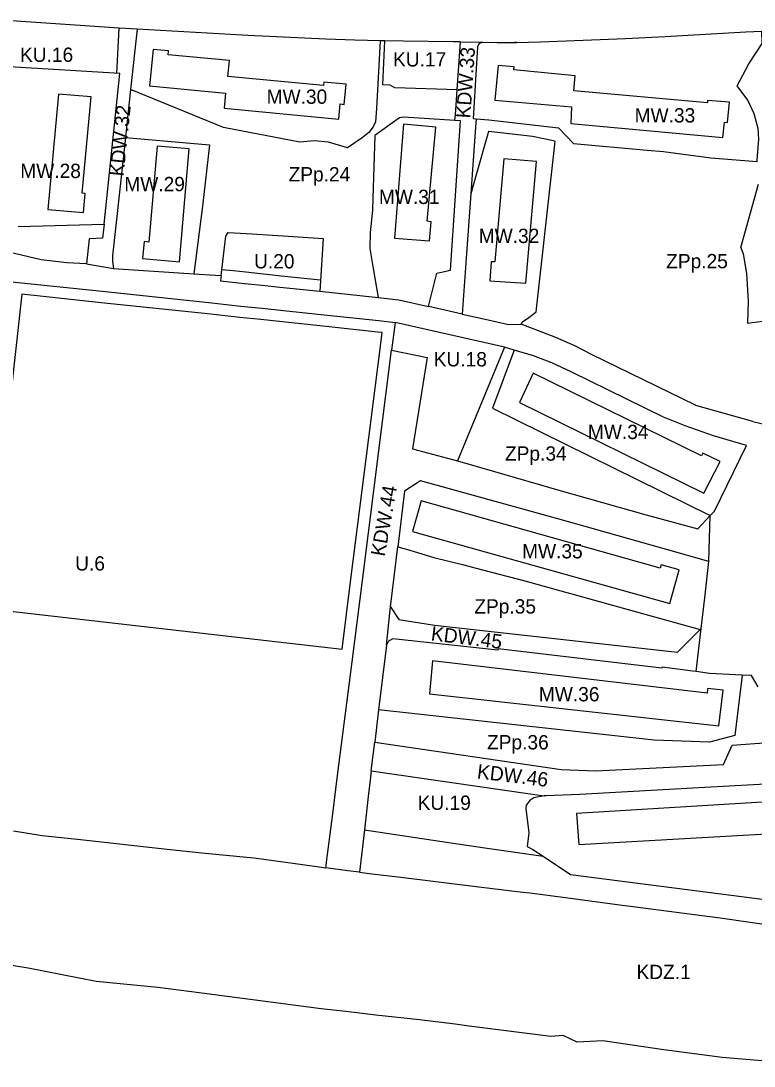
# Model space of a CAD drawing. Extents: x 7424434 to 7425898, y 5541432 to 5542659.
# Drawn here: x 7424993.9 to 7425250.1, y 5541470.1 to 5541835.1 of the extents above; entities that cross this region are included whole.
import ezdxf

# ---------------------------------------------------------------- set-up
doc = ezdxf.new("R2010")
doc.units = 0
for name, color, linetype in [('linie rozgraniczające', 7, 'Continuous'), ('nieprzekraczalne linie zabudowy', 7, 'Continuous'), ('obowiazujace linie zabudowy', 7, 'Continuous'), ('przeznaczenia terenów', 7, 'Continuous')]:
    doc.layers.add(name, color=color, linetype=linetype)

msp = doc.modelspace()

# ---------------------------------------------------------------- linework, layer by layer
at = {"layer": 'linie rozgraniczające'}
for p, q in [((7425028.31, 5541832.6), (7424990.69, 5541835.14)), ((7425027.41, 5541816.82), (7425028.31, 5541832.6)), ((7425034.51, 5541832.21), (7425028.31, 5541832.6)), ((7425034.51, 5541832.21), (7425032.26, 5541811.15)), ((7425071.28, 5541830.18), (7425034.51, 5541832.21)), ((7425073.25, 5541830.08), (7425071.28, 5541830.18)), ((7425100.46, 5541828.73), (7425073.25, 5541830.08)), ((7425110.62, 5541828.41), (7425100.46, 5541828.73)), ((7425119.42, 5541828.23), (7425110.62, 5541828.41)), ((7425119.42, 5541828.23), (7425118.19, 5541804.6)), ((7425121.11, 5541828.19), (7425119.42, 5541828.23)), ((7425120.42, 5541812.76), (7425121.11, 5541828.19)), ((7425127.58, 5541828.06), (7425121.11, 5541828.19)), ((7425144.98, 5541827.83), (7425127.58, 5541828.06)), ((7425147.53, 5541827.8), (7425144.98, 5541827.83)), ((7425146.35, 5541811.09), (7425147.53, 5541827.8)), ((7425147.53, 5541827.8), (7425155.16, 5541827.7)), ((7425153.88, 5541827.17), (7425153.49, 5541826.05)), ((7425155.16, 5541827.7), (7425153.88, 5541827.17)), ((7425167.04, 5541827.57), (7425166.42, 5541827.54)), ((7425153.49, 5541826.05), (7425151.91, 5541801.1)), ((7425028.52, 5541816.75), (7424990.01, 5541819.09)), ((7425023, 5541764.15), (7425028.52, 5541816.75)), ((7425122.97, 5541812.69), (7425120.42, 5541812.76)), ((7425124.56, 5541811.72), (7425122.97, 5541812.69)), ((7425244.17, 5541812.41), (7425244.15, 5541812.44)), ((7425032.26, 5541811.15), (7425031.31, 5541802.3)), ((7425064.78, 5541797.93), (7425032.26, 5541811.15)), ((7425146.35, 5541811.09), (7425124.56, 5541811.72)), ((7425145.73, 5541802.29), (7425146.35, 5541811.09)), ((7425118.19, 5541804.6), (7425117.8, 5541799.93)), ((7425031.31, 5541802.3), (7425030.45, 5541794.37)), ((7425126.23, 5541801.26), (7425117.65, 5541795.16)), ((7425127.62, 5541801.48), (7425126.23, 5541801.26)), ((7425145.59, 5541800.33), (7425127.62, 5541801.48)), ((7425145.59, 5541800.33), (7425145.73, 5541802.29)), ((7425151.91, 5541801.1), (7425151.91, 5541801.08)), ((7425151.91, 5541801.08), (7425152.86, 5541800.99)), ((7425152.96, 5541800.98), (7425152.79, 5541797.98)), ((7425152.86, 5541800.99), (7425152.96, 5541800.98)), ((7425068.93, 5541797.14), (7425064.78, 5541797.93)), ((7425117.06, 5541798.15), (7425115.54, 5541796.17)), ((7425117.8, 5541799.93), (7425117.06, 5541798.15)), ((7425144.06, 5541748.1), (7425147.47, 5541800.22)), ((7425147.47, 5541800.22), (7425145.59, 5541800.33)), ((7425152.79, 5541797.98), (7425151.59, 5541781.54)), ((7425030.45, 5541794.37), (7425026, 5541753.15)), ((7425030.45, 5541794.37), (7425059.82, 5541791.9)), ((7425070.83, 5541796.77), (7425068.93, 5541797.14)), ((7425091.42, 5541792.78), (7425070.83, 5541796.77)), ((7425113.12, 5541794.27), (7425108.03, 5541790.86)), ((7425115.54, 5541796.17), (7425113.12, 5541794.27)), ((7425117.65, 5541795.16), (7425116.94, 5541773.19)), ((7425157.3, 5541796.55), (7425153.01, 5541781.44)), ((7425157.39, 5541796.54), (7425157.3, 5541796.55)), ((7425172.69, 5541794.82), (7425157.39, 5541796.54)), ((7425180.04, 5541793.26), (7425172.69, 5541794.82)), ((7425059.82, 5541791.9), (7425057.43, 5541770.49)), ((7425096.41, 5541793.22), (7425091.42, 5541792.78)), ((7425101.38, 5541792.8), (7425096.41, 5541793.22)), ((7425108.03, 5541790.86), (7425101.38, 5541792.8)), ((7425173.97, 5541733.5), (7425180.57, 5541793)), ((7425180.57, 5541793), (7425180.04, 5541793.26)), ((7425151.59, 5541781.54), (7425151.12, 5541774.78)), ((7425153.01, 5541781.44), (7425151.12, 5541774.78)), ((7425245.41, 5541755.97), (7425251.69, 5541778.11)), ((7425116.94, 5541773.19), (7425116.76, 5541769)), ((7425151.12, 5541774.78), (7425149.65, 5541753.87)), ((7425057.43, 5541770.49), (7425054.35, 5541746.8)), ((7425116.76, 5541769), (7425115.95, 5541761.28)), ((7424993.02, 5541763.29), (7425023, 5541764.15)), ((7425023, 5541764.15), (7425022.46, 5541759.23)), ((7425065.56, 5541760.01), (7425066.41, 5541761.24)), ((7425066.41, 5541761.24), (7425074.7, 5541760.73)), ((7425074.7, 5541760.73), (7425081.83, 5541760.29)), ((7425115.95, 5541761.28), (7425115.87, 5541755.69)), ((7425001, 5541751.75), (7424967.07, 5541759.6)), ((7425017.81, 5541759.01), (7425016.91, 5541750.32)), ((7425022.46, 5541759.23), (7425017.81, 5541759.01)), ((7425063.87, 5541746.18), (7425065.56, 5541760.01)), ((7425081.83, 5541760.29), (7425085.54, 5541760.06)), ((7425085.54, 5541760.06), (7425089.03, 5541759.84)), ((7425089.03, 5541759.84), (7425099.52, 5541759.18)), ((7425099.52, 5541759.18), (7425098.33, 5541740.7)), ((7425115.87, 5541755.69), (7425116.96, 5541748.69)), ((7425149.65, 5541753.87), (7425148.16, 5541732.75)), ((7425245.41, 5541755.97), (7425246.32, 5541753.8)), ((7425246.32, 5541753.8), (7425247.45, 5541746.94)), ((7425009.97, 5541750.67), (7425001, 5541751.75)), ((7425016.91, 5541750.32), (7425009.97, 5541750.67)), ((7425016.91, 5541750.32), (7425026.3, 5541748.63)), ((7425026, 5541753.15), (7425025.93, 5541751.08)), ((7425025.93, 5541751.08), (7425026.3, 5541748.63)), ((7425026.3, 5541748.63), (7425054.35, 5541746.8)), ((7425054.35, 5541746.8), (7425061.93, 5541746.31)), ((7425061.93, 5541746.31), (7425063.87, 5541746.18)), ((7425063.87, 5541746.18), (7425063.65, 5541744.38)), ((7425116.96, 5541748.69), (7425118.82, 5541738.53)), ((7425136.4, 5541735.41), (7425139.22, 5541746.99)), ((7425139.22, 5541746.99), (7425144.06, 5541748.1)), ((7425247.45, 5541746.94), (7425248.03, 5541737.25)), ((7424990.77, 5541744.06), (7425022.36, 5541740.71)), ((7425063.65, 5541744.38), (7425072.04, 5541743.49)), ((7425072.04, 5541743.49), (7425072.13, 5541743.48)), ((7425072.13, 5541743.48), (7425079.34, 5541742.72)), ((7425079.34, 5541742.72), (7425084.4, 5541742.18)), ((7425022.36, 5541740.71), (7425060.68, 5541736.65)), ((7425084.4, 5541742.18), (7425086.74, 5541741.93)), ((7425086.74, 5541741.93), (7425098.33, 5541740.7)), ((7425098.33, 5541740.7), (7425118.82, 5541738.53)), ((7425060.68, 5541736.65), (7425062.67, 5541736.44)), ((7425062.67, 5541736.44), (7425070.83, 5541735.57)), ((7425070.83, 5541735.57), (7425078.22, 5541734.79)), ((7425118.82, 5541738.53), (7425119.79, 5541738.43)), ((7425119.79, 5541738.43), (7425125.99, 5541737.77)), ((7425125.99, 5541737.77), (7425136.4, 5541735.41)), ((7425136.43, 5541735.4), (7425136.4, 5541735.41)), ((7425148.16, 5541732.75), (7425136.43, 5541735.4)), ((7425248.03, 5541737.25), (7425247.77, 5541729.63)), ((7425078.22, 5541734.79), (7425085.73, 5541733.99)), ((7425085.73, 5541733.99), (7425102.08, 5541732.26)), ((7425102.08, 5541732.26), (7425118.94, 5541730.47)), ((7425148.16, 5541732.75), (7425156.13, 5541730.95)), ((7425169.14, 5541730.04), (7425171.42, 5541731.54)), ((7425171.42, 5541731.54), (7425173.97, 5541733.5)), ((7425247.77, 5541729.63), (7425271.72, 5541732.74)), ((7425118.94, 5541730.47), (7425124.68, 5541729.86)), ((7425124.68, 5541729.86), (7425123.45, 5541720.14)), ((7425162.92, 5541721.21), (7425124.68, 5541729.86)), ((7425156.13, 5541730.95), (7425164.34, 5541729.09)), ((7425164.34, 5541729.09), (7425168.69, 5541729.22)), ((7425168.69, 5541729.22), (7425169.14, 5541730.04)), ((7425180.87, 5541724.58), (7425168.69, 5541729.22)), ((7425187.45, 5541721.69), (7425180.87, 5541724.58)), ((7425162.92, 5541721.21), (7425146.44, 5541681.46)), ((7425166.24, 5541720.2), (7425162.92, 5541721.21)), ((7425193.3, 5541718.61), (7425187.45, 5541721.69)), ((7425119.46, 5541688.71), (7425123.45, 5541720.14)), ((7425123.45, 5541720.14), (7425135.88, 5541717.63)), ((7425135.88, 5541717.63), (7425130.73, 5541685.68)), ((7425166.24, 5541720.2), (7425158.69, 5541699.86)), ((7425173.01, 5541718.13), (7425166.24, 5541720.2)), ((7425179.38, 5541715.76), (7425173.01, 5541718.13)), ((7425229.68, 5541700.98), (7425193.3, 5541718.61)), ((7425186.37, 5541712.5), (7425179.38, 5541715.76)), ((7425218.48, 5541696.73), (7425186.37, 5541712.5)), ((7425158.69, 5541699.86), (7425234.78, 5541662.36)), ((7425229.8, 5541700.85), (7425229.68, 5541700.98)), ((7425249.71, 5541695.25), (7425229.8, 5541700.85)), ((7425225.99, 5541693.7), (7425218.48, 5541696.73)), ((7425249.71, 5541695.25), (7425267.02, 5541691.03)), ((7425235.87, 5541690.28), (7425225.99, 5541693.7)), ((7425113.24, 5541639.69), (7425119.46, 5541688.71)), ((7425247.45, 5541686.81), (7425235.87, 5541690.28)), ((7425130.73, 5541685.68), (7425146.44, 5541681.46)), ((7425236.3, 5541663.95), (7425247.45, 5541686.81)), ((7425146.44, 5541681.46), (7425159.36, 5541677.75)), ((7425159.36, 5541677.75), (7425159.37, 5541677.75)), ((7425159.37, 5541677.75), (7425181.91, 5541671.28)), ((7425133.56, 5541674.52), (7425127.97, 5541670.92)), ((7425181.58, 5541661.22), (7425133.56, 5541674.52)), ((7425127.97, 5541670.92), (7425125.64, 5541651.47)), ((7425181.91, 5541671.28), (7425212.36, 5541662.7)), ((7425212.36, 5541662.7), (7425230.4, 5541657.81)), ((7425230.4, 5541657.81), (7425234.78, 5541662.36)), ((7425234.31, 5541646.31), (7425234.78, 5541662.36)), ((7425234.78, 5541662.36), (7425236.3, 5541663.95)), ((7425191.86, 5541658.32), (7425181.58, 5541661.22)), ((7425219.49, 5541650.5), (7425191.86, 5541658.32)), ((7425123.12, 5541630.49), (7425125.64, 5541651.47)), ((7425125.64, 5541651.47), (7425129.79, 5541650.25)), ((7425129.79, 5541650.25), (7425138.22, 5541647.76)), ((7425138.22, 5541647.76), (7425148.7, 5541645.13)), ((7425234.31, 5541646.31), (7425219.49, 5541650.5)), ((7425148.7, 5541645.13), (7425152.5, 5541644.15)), ((7425152.5, 5541644.15), (7425170.03, 5541639.63)), ((7425232.85, 5541633.66), (7425234.31, 5541646.31)), ((7425109.64, 5541611.33), (7425113.24, 5541639.69)), ((7425170.03, 5541639.63), (7425231.29, 5541622.64)), ((7425231.61, 5541622.96), (7425232.85, 5541633.66)), ((7425121.64, 5541617.12), (7425123.12, 5541630.49)), ((7425123.12, 5541630.49), (7425125.93, 5541626.08)), ((7425125.93, 5541626.08), (7425138.48, 5541624.13)), ((7425138.48, 5541624.13), (7425139.44, 5541623.96)), ((7425139.44, 5541623.96), (7425182.51, 5541619.2)), ((7425223.33, 5541614.65), (7425231.29, 5541622.64)), ((7425229.87, 5541607.89), (7425231.61, 5541622.96)), ((7425231.29, 5541622.64), (7425231.61, 5541622.96)), ((7425122.36, 5541618.5), (7425121.64, 5541617.12)), ((7425123.94, 5541619.33), (7425122.36, 5541618.5)), ((7425160.54, 5541615.35), (7425123.94, 5541619.33)), ((7425182.51, 5541619.2), (7425223.33, 5541614.65)), ((7425121.64, 5541617.12), (7425118.92, 5541594.6)), ((7425160.65, 5541615.87), (7425160.54, 5541615.35)), ((7425217.88, 5541609.1), (7425160.65, 5541615.87)), ((7425105.05, 5541575.17), (7425109.64, 5541611.33)), ((7425217.93, 5541609.49), (7425217.88, 5541609.1)), ((7425228.7, 5541608.05), (7425217.93, 5541609.49)), ((7425229.87, 5541607.89), (7425228.7, 5541608.05)), ((7425234.51, 5541607.27), (7425229.87, 5541607.89)), ((7425245.95, 5541606.65), (7425234.51, 5541607.27)), ((7425245.95, 5541606.65), (7425243.38, 5541585.64)), ((7425249.19, 5541606.48), (7425245.95, 5541606.65)), ((7425251.53, 5541602.63), (7425249.19, 5541606.48)), ((7425118.92, 5541594.6), (7425117.55, 5541583.23)), ((7425215.22, 5541583.91), (7425118.92, 5541594.6)), ((7425243.38, 5541585.64), (7425234.54, 5541583.28)), ((7425116.35, 5541573.3), (7425117.55, 5541583.23)), ((7425117.55, 5541583.23), (7425182.73, 5541573.69)), ((7425234.54, 5541583.28), (7425215.22, 5541583.91)), ((7425239.43, 5541575.44), (7425242.41, 5541582.21)), ((7425242.41, 5541582.21), (7425258.28, 5541583.33)), ((7425104.6, 5541571.65), (7425105.05, 5541575.17)), ((7425194.77, 5541573.24), (7425239.43, 5541575.44)), ((7425102.89, 5541558.2), (7425104.6, 5541571.65)), ((7425116.35, 5541573.3), (7425115.82, 5541568.89)), ((7425116.35, 5541573.3), (7425171.92, 5541565.17)), ((7425182.73, 5541573.69), (7425194.77, 5541573.24)), ((7425115.82, 5541568.89), (7425115.39, 5541565.3)), ((7425232.84, 5541567.44), (7425189.16, 5541564.94)), ((7425258.79, 5541568.83), (7425232.84, 5541567.44)), ((7425115.39, 5541565.3), (7425113.95, 5541552.6)), ((7425173.15, 5541563.84), (7425171.78, 5541562.87)), ((7425171.92, 5541565.17), (7425176.76, 5541564.46)), ((7425176.76, 5541564.46), (7425173.15, 5541563.84)), ((7425177.42, 5541564.57), (7425176.76, 5541564.46)), ((7425189.16, 5541564.94), (7425177.42, 5541564.57)), ((7425170.44, 5541561.27), (7425170.41, 5541560.06)), ((7425170.41, 5541560.06), (7425171.36, 5541551.6)), ((7425171.78, 5541562.87), (7425170.44, 5541561.27)), ((7425100.76, 5541541.38), (7425102.89, 5541558.2)), ((7425113.95, 5541552.6), (7425112.27, 5541537.8)), ((7425113.95, 5541552.6), (7425142.66, 5541548.37)), ((7424991.33, 5541552.3), (7425001.36, 5541550.71)), ((7425001.36, 5541550.71), (7425013.67, 5541549.35)), ((7425013.67, 5541549.35), (7425045, 5541545.88)), ((7425171.36, 5541551.6), (7425170.85, 5541546.81)), ((7425045, 5541545.88), (7425057.11, 5541544.65)), ((7425142.66, 5541548.37), (7425156.85, 5541546.28)), ((7425156.85, 5541546.28), (7425167.44, 5541544.72)), ((7425170.85, 5541546.81), (7425172.76, 5541545.82)), ((7425172.76, 5541545.82), (7425176.42, 5541543.4)), ((7425057.11, 5541544.65), (7425075.34, 5541542.81)), ((7425075.34, 5541542.81), (7425076.23, 5541542.69)), ((7425076.23, 5541542.69), (7425092.3, 5541540.51)), ((7425167.44, 5541544.72), (7425176.42, 5541543.4)), ((7425176.42, 5541543.4), (7425186.01, 5541537.05)), ((7425092.3, 5541540.51), (7425098.19, 5541539.71)), ((7425098.19, 5541539.71), (7425100.5, 5541539.4)), ((7425100.5, 5541539.4), (7425100.59, 5541540.04)), ((7425108.15, 5541538.36), (7425100.5, 5541539.4)), ((7425100.59, 5541540.04), (7425100.76, 5541541.38)), ((7425112.27, 5541537.8), (7425108.15, 5541538.36)), ((7425112.27, 5541537.8), (7425116.57, 5541537.28)), ((7425116.57, 5541537.28), (7425125.72, 5541536.17)), ((7425125.72, 5541536.17), (7425139.8, 5541534.47)), ((7425139.8, 5541534.47), (7425153.94, 5541532.76)), ((7425186.01, 5541537.05), (7425278.62, 5541525.09)), ((7425153.94, 5541532.76), (7425169.36, 5541530.89)), ((7425169.36, 5541530.89), (7425171.71, 5541530.61)), ((7425171.71, 5541530.61), (7425184.2, 5541528.97)), ((7425184.2, 5541528.97), (7425197.11, 5541527.28)), ((7425197.11, 5541527.28), (7425203.98, 5541526.38)), ((7425203.98, 5541526.38), (7425205.94, 5541526.13)), ((7425205.94, 5541526.13), (7425216.65, 5541524.72)), ((7425216.65, 5541524.72), (7425238.22, 5541521.9)), ((7425238.22, 5541521.9), (7425264.19, 5541518.15)), ((7424996.45, 5541504.28), (7424951.51, 5541511.66)), ((7425020.25, 5541499.64), (7424996.45, 5541504.28)), ((7425041.75, 5541497.61), (7425020.25, 5541499.64)), ((7425057.2, 5541495.59), (7425041.75, 5541497.61)), ((7425066.01, 5541494.43), (7425057.2, 5541495.59)), ((7425083.88, 5541492.09), (7425066.01, 5541494.43)), ((7425098.9, 5541490.12), (7425083.88, 5541492.09)), ((7425107.51, 5541489.15), (7425098.9, 5541490.12)), ((7425117.95, 5541487.96), (7425107.51, 5541489.15)), ((7425133.15, 5541486.23), (7425117.95, 5541487.96)), ((7425145.65, 5541484.82), (7425133.15, 5541486.23)), ((7425148.08, 5541484.47), (7425145.65, 5541484.82)), ((7425150.56, 5541484.12), (7425148.08, 5541484.47)), ((7425179.05, 5541480.47), (7425150.56, 5541484.12)), ((7425183.34, 5541480.84), (7425179.05, 5541480.47)), ((7425188.24, 5541478.54), (7425183.34, 5541480.84)), ((7425197.23, 5541479), (7425188.24, 5541478.54)), ((7425218.57, 5541475.77), (7425197.23, 5541479)), ((7425238.89, 5541473.19), (7425218.57, 5541475.77)), ((7425274.44, 5541470.13), (7425238.89, 5541473.19))]:
    msp.add_line(p, q, dxfattribs=at)
for points in [[(7425152.96, 5541800.98), (7425157.45, 5541800.54), (7425181.73, 5541797.75), (7425186.96, 5541792.35), (7425212.77, 5541790.02), (7425218.43, 5541789.51), (7425235.03, 5541787.34), (7425251.17, 5541786.09), (7425251.22, 5541786.51), (7425251.78, 5541793.87), (7425251.55, 5541797.6), (7425250.15, 5541802.68), (7425247.92, 5541807.48), (7425244.17, 5541812.41), (7425244.15, 5541812.44), (7425248.22, 5541820.16), (7425252.92, 5541827.21), (7425252.8, 5541831.58)], [(7425155.16, 5541827.7), (7425160.36, 5541827.63), (7425166.42, 5541827.54), (7425167.04, 5541827.57), (7425175.52, 5541827.87), (7425190.4, 5541828.41), (7425205.13, 5541828.95), (7425219.03, 5541829.71), (7425247.23, 5541831.37), (7425252.8, 5541831.58)]]:
    msp.add_lwpolyline(points, dxfattribs=at)
at = {"layer": 'nieprzekraczalne linie zabudowy'}
msp.add_lwpolyline([(7425064.13, 5541748.35), (7425068.11, 5541747.93), (7425072.55, 5541747.46), (7425079.77, 5541746.69), (7425084.82, 5541746.15), (7425087.16, 5541745.91), (7425098.59, 5541744.7)], dxfattribs=at)
msp.add_lwpolyline([(7425106.17, 5541615.78), (7425109.27, 5541640.19), (7425119.48, 5541720.64), (7425120.2, 5541726.31), (7425118.52, 5541726.49), (7425101.66, 5541728.28), (7425085.31, 5541730.01), (7425077.8, 5541730.81), (7425070.41, 5541731.59), (7425062.25, 5541732.46), (7425060.26, 5541732.67), (7425021.94, 5541736.73), (7424994.3, 5541739.66), (7424990.42, 5541704.86), (7424982.04, 5541629.92)], close=True, dxfattribs=at)
at = {"layer": 'obowiazujace linie zabudowy'}
for points in [[(7425040.1, 5541825.14), (7425038.92, 5541812.41), (7425065.45, 5541809.92), (7425064.94, 5541804.63), (7425105.02, 5541800.86), (7425105.53, 5541806.12), (7425106.86, 5541805.99), (7425107.54, 5541813.01), (7425099.81, 5541813.76), (7425099.69, 5541812.54), (7425066.29, 5541815.67), (7425066.82, 5541821.32), (7425045.34, 5541823.33), (7425045.46, 5541824.64)], [(7425159.5, 5541807.41), (7425186.36, 5541805.14), (7425186.03, 5541799.34), (7425239.23, 5541794.46), (7425239.71, 5541799.72), (7425240.81, 5541799.62), (7425241.47, 5541806.8), (7425233.87, 5541807.39), (7425233.8, 5541806.48), (7425187.09, 5541810.76), (7425187.57, 5541815.92), (7425166.2, 5541818.07), (7425166.3, 5541819.05), (7425160.71, 5541819.61)], [(7425003.3, 5541769.23), (7425015.86, 5541768.22), (7425016.37, 5541774.92), (7425015.34, 5541775.01), (7425018.52, 5541808.62), (7425007.1, 5541809.58)], [(7425136.67, 5541758.35), (7425137.26, 5541764.97), (7425135.88, 5541765.15), (7425138.86, 5541798.06), (7425127.67, 5541799.06), (7425124.49, 5541759.3)], [(7425049.39, 5541751.03), (7425052.73, 5541790.49), (7425041.53, 5541791.43), (7425038.7, 5541757.92), (7425036.96, 5541758.07), (7425036.46, 5541752.12)], [(7425157.79, 5541744.4), (7425170.39, 5541743.56), (7425174.03, 5541786.01), (7425162.65, 5541786.95), (7425159.5, 5541750.96), (7425158.2, 5541750.98)], [(7425232.49, 5541670.18), (7425238.29, 5541681.24), (7425232.2, 5541684.23), (7425231.73, 5541683.26), (7425172.97, 5541712.1), (7425168.13, 5541701.9)], [(7425130.79, 5541656.87), (7425220.61, 5541631.67), (7425223.91, 5541643.48), (7425217.59, 5541645.21), (7425217.27, 5541644.04), (7425133.74, 5541667.53)], [(7425136.71, 5541600.18), (7425237.74, 5541588.96), (7425239.26, 5541601.37), (7425233.82, 5541601.94), (7425233.68, 5541600.42), (7425137.79, 5541611.61)], [(7425188.91, 5541547.52), (7425281.23, 5541552.74), (7425280.57, 5541565.14), (7425273.91, 5541564.73), (7425273.98, 5541563.61), (7425188.07, 5541558.37)]]:
    msp.add_lwpolyline(points, close=True, dxfattribs=at)

# ---------------------------------------------------------------- texts
at = {"layer": 'przeznaczenia terenów'}
for s, p in [('KU.16', (7424993.63, 5541820.83)), ('KU.17', (7425123.96, 5541819.22)), ('MW.30', (7425079.79, 5541806.18)), ('MW.33', (7425208.36, 5541799.66)), ('MW.28', (7424993.73, 5541780.26)), ('ZPp.24', (7425087.46, 5541779.08)), ('MW.29', (7425030.07, 5541775.67)), ('MW.31', (7425119.03, 5541771.19)), ('MW.32', (7425153.89, 5541757.56)), ('U.20', (7425075.41, 5541748.7)), ('ZPp.25', (7425219.37, 5541748.74)), ('KU.18', (7425138.16, 5541714.48)), ('MW.34', (7425192.04, 5541689.11)), ('ZPp.34', (7425163.06, 5541681.56)), ('MW.35', (7425169.04, 5541647.44)), ('U.6', (7425012.91, 5541643.18)), ('ZPp.35', (7425152.35, 5541628.17)), ('MW.36', (7425174.9, 5541597.51)), ('ZPp.36', (7425156.79, 5541580.73)), ('KU.19', (7425132.56, 5541559.6)), ('KDZ.1', (7425209.01, 5541500.52))]:
    msp.add_text(s, height=5, dxfattribs=at).set_placement(p)
for s, rotation, p in [('KDW.33', 86.1016, (7425150.94, 5541801)), ('KDW.32', 84.0942, (7425029.79, 5541780.69)), ('KDW.44', 80, (7425121.05, 5541647.9)), ('KDW.45', 353, (7425137.02, 5541618.83)), ('KDW.46', 353, (7425153.12, 5541570.65))]:
    msp.add_text(s, height=5, rotation=rotation, dxfattribs=at).set_placement(p)

doc.saveas('drawing.dxf')
